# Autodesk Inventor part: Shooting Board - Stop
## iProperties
Created: 2010-08
Part Number: Shooting Board - Stop
Material: Default
Document SubType Name: Modeling
Designer: Paul Munford
Density: 1 g/cm^3
Author: Paul Munford
Length: 125 mm
Width: 19 mm
Thickness: 19 mm
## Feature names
1. Extrusion1
